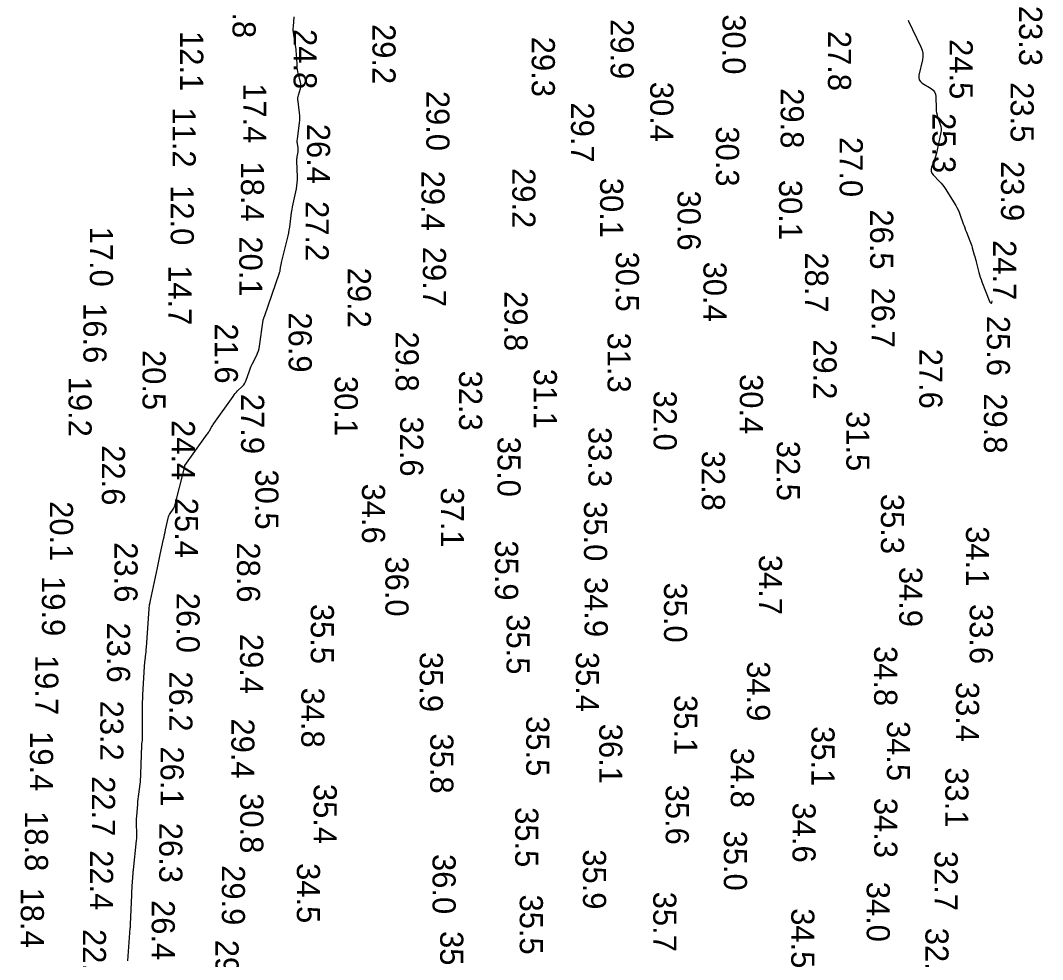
# Model space of a CAD drawing. Extents: x 1178573 to 1187098, y 693282 to 751751.
# Drawn here: x 1179064 to 1179617, y 708713 to 709221 of the extents above; entities that cross this region are included whole.
import ezdxf

# ---------------------------------------------------------------- set-up
doc = ezdxf.new("R2010")
doc.units = 0
doc.layers.add('V-HYDS-MAJR', color=7, linetype='Continuous')
doc.layers.add('V-HYDS-SOUN', color=7, linetype='Continuous')

msp = doc.modelspace()

# ---------------------------------------------------------------- linework, layer by layer
at = {"layer": 'V-HYDS-MAJR'}
for points in [[(1179122.48, 708712.53), (1179123.74, 708730.3), (1179123.75, 708730.48), (1179123.77, 708730.65), (1179123.78, 708730.83), (1179123.79, 708731), (1179123.83, 708731.7), (1179123.85, 708731.87), (1179123.86, 708732.05), (1179123.86, 708732.22), (1179123.87, 708732.4), (1179124.54, 708748.04), (1179124.59, 708749.27), (1179124.66, 708750.5), (1179124.73, 708751.73), (1179124.81, 708752.96), (1179125.28, 708760.05), (1179125.29, 708760.2), (1179125.3, 708760.34), (1179125.31, 708760.48), (1179125.33, 708760.62), (1179125.38, 708761.19), (1179125.4, 708761.34), (1179125.41, 708761.48), (1179125.43, 708761.62), (1179125.44, 708761.76), (1179127.13, 708777.71), (1179127.22, 708778.79), (1179127.28, 708779.86), (1179127.3, 708780.94), (1179127.28, 708782.02), (1179127.14, 708786.34), (1179127.12, 708787.42), (1179127.13, 708788.5), (1179127.17, 708789.58), (1179127.24, 708790.65), (1179127.75, 708797.37), (1179127.86, 708798.72), (1179128, 708800.06), (1179128.15, 708801.41), (1179128.32, 708802.75), (1179129.04, 708808.11), (1179129.21, 708809.46), (1179129.34, 708810.8), (1179129.43, 708812.15), (1179129.49, 708813.5), (1179129.99, 708829.25), (1179130.01, 708829.61), (1179130.03, 708829.98), (1179130.06, 708830.35), (1179130.1, 708830.72), (1179130.26, 708832.19), (1179130.3, 708832.56), (1179130.32, 708832.93), (1179130.34, 708833.29), (1179130.34, 708833.66), (1179130.26, 708850.45), (1179130.26, 708850.94), (1179130.27, 708851.44), (1179130.3, 708851.94), (1179130.33, 708852.43), (1179130.47, 708854.42), (1179130.5, 708854.91), (1179130.53, 708855.41), (1179130.56, 708855.91), (1179130.59, 708856.4), (1179131.41, 708871.76), (1179131.46, 708872.62), (1179131.53, 708873.47), (1179131.62, 708874.33), (1179131.72, 708875.19), (1179132.15, 708878.61), (1179132.25, 708879.46), (1179132.34, 708880.32), (1179132.41, 708881.17), (1179132.48, 708882.03), (1179133.88, 708902.93), (1179133.9, 708903.12), (1179133.91, 708903.3), (1179133.94, 708903.48), (1179133.96, 708903.67), (1179134.08, 708904.4), (1179134.11, 708904.58), (1179134.14, 708904.76), (1179134.17, 708904.94), (1179134.2, 708905.12), (1179134.46, 708906.44), (1179134.52, 708906.72), (1179134.57, 708906.99), (1179134.63, 708907.27), (1179134.69, 708907.55), (1179138.4, 708925.16), (1179138.79, 708926.97), (1179139.18, 708928.77), (1179139.57, 708930.58), (1179139.96, 708932.39), (1179141.77, 708940.68), (1179142.05, 708941.95), (1179142.32, 708943.23), (1179142.6, 708944.5), (1179142.87, 708945.77), (1179144.19, 708952.04), (1179144.36, 708952.71), (1179144.6, 708953.36), (1179144.9, 708953.97), (1179145.26, 708954.56), (1179146.85, 708956.87), (1179147.21, 708957.46), (1179147.53, 708958.07), (1179147.78, 708958.71), (1179147.98, 708959.38), (1179152.87, 708978.62), (1179152.91, 708978.79), (1179152.95, 708978.96), (1179152.99, 708979.13), (1179153.02, 708979.3), (1179153.2, 708980.28), (1179153.21, 708980.31), (1179153.21, 708980.34), (1179153.22, 708980.37), (1179153.22, 708980.4), (1179153.24, 708980.53), (1179153.25, 708980.56), (1179153.26, 708980.59), (1179153.27, 708980.62), (1179153.29, 708980.65), (1179165.32, 708997.48), (1179165.64, 708997.95), (1179165.96, 708998.43), (1179166.27, 708998.91), (1179166.56, 708999.4), (1179167.72, 709001.37), (1179168.02, 709001.86), (1179168.32, 709002.34), (1179168.64, 709002.82), (1179168.97, 709003.29), (1179179.35, 709017.98), (1179179.91, 709018.74), (1179180.51, 709019.48), (1179181.13, 709020.19), (1179181.78, 709020.88), (1179184.45, 709023.57), (1179185.07, 709024.27), (1179185.6, 709025.03), (1179186.04, 709025.84), (1179186.39, 709026.71), (1179187.94, 709031.26), (1179188.31, 709032.31), (1179188.73, 709033.34), (1179189.17, 709034.36), (1179189.65, 709035.37), (1179192.09, 709040.27), (1179192.61, 709041.43), (1179193.03, 709042.63), (1179193.36, 709043.85), (1179193.59, 709045.11), (1179195.6, 709059.25), (1179195.62, 709059.36), (1179195.64, 709059.47), (1179195.67, 709059.58), (1179195.7, 709059.69), (1179195.86, 709060.17), (1179195.89, 709060.26), (1179195.92, 709060.34), (1179195.95, 709060.42), (1179195.98, 709060.5), (1179196.13, 709060.83), (1179196.16, 709060.91), (1179196.2, 709060.99), (1179196.23, 709061.07), (1179196.26, 709061.16), (1179204.34, 709084.74), (1179204.38, 709084.87), (1179204.43, 709085.01), (1179204.47, 709085.14), (1179204.51, 709085.27), (1179204.69, 709085.79), (1179204.73, 709085.93), (1179204.76, 709086.06), (1179204.79, 709086.19), (1179204.82, 709086.33), (1179205.2, 709088.71), (1179205.27, 709089.15), (1179205.35, 709089.59), (1179205.45, 709090.03), (1179205.55, 709090.47), (1179209.03, 709104.9), (1179209.39, 709106.45), (1179209.7, 709108), (1179209.96, 709109.56), (1179210.18, 709111.14), (1179210.99, 709117.44), (1179211.21, 709119.01), (1179211.46, 709120.58), (1179211.75, 709122.14), (1179212.08, 709123.69), (1179213.54, 709130.28), (1179213.84, 709131.87), (1179214.03, 709133.46), (1179214.13, 709135.07), (1179214.13, 709136.68), (1179213.83, 709145.14), (1179213.83, 709145.77), (1179213.85, 709146.4), (1179213.92, 709147.02), (1179214.01, 709147.65), (1179214.47, 709150.26), (1179214.55, 709150.82), (1179214.57, 709151.39), (1179214.55, 709151.95), (1179214.49, 709152.52), (1179214.12, 709154.78), (1179214.05, 709155.34), (1179214.02, 709155.91), (1179214.03, 709156.48), (1179214.09, 709157.04), (1179215.24, 709166.01), (1179215.37, 709167.34), (1179215.41, 709168.66), (1179215.36, 709169.99), (1179215.23, 709171.32), (1179214.43, 709177.5), (1179214.36, 709178.39), (1179214.38, 709179.27), (1179214.5, 709180.15), (1179214.71, 709181.02), (1179215.75, 709184.47), (1179215.94, 709185.34), (1179216.02, 709186.21), (1179215.98, 709187.08), (1179215.81, 709187.95), (1179214.57, 709192.7), (1179214.33, 709193.75), (1179214.14, 709194.81), (1179214.01, 709195.88), (1179213.94, 709196.96), (1179213.76, 709201.28), (1179213.7, 709202.36), (1179213.61, 709203.43), (1179213.49, 709204.51), (1179213.34, 709205.58), (1179212.08, 709213.7), (1179211.94, 709214.8), (1179211.87, 709215.91), (1179211.87, 709217.01), (1179211.93, 709218.12), (1179212.4, 709223.4)], [(1179544.25, 709221.49), (1179544.5, 709220.9), (1179551.25, 709207.06), (1179551.92, 709205.35), (1179552.28, 709203.6), (1179552.33, 709201.82), (1179552.06, 709200), (1179550.16, 709191.74), (1179550.04, 709190.44), (1179550.29, 709189.3), (1179550.92, 709188.32), (1179551.94, 709187.5), (1179556.75, 709184.52), (1179557.81, 709183.7), (1179558.58, 709182.7), (1179559.06, 709181.54), (1179559.25, 709180.21), (1179559.46, 709173.53), (1179559.54, 709172.43), (1179559.69, 709171.35), (1179559.93, 709170.29), (1179560.24, 709169.24), (1179561.65, 709165.06), (1179561.94, 709164.02), (1179562.08, 709162.96), (1179562.08, 709161.89), (1179561.93, 709160.81), (1179560.09, 709151.42), (1179559.82, 709150.21), (1179559.51, 709149.01), (1179559.15, 709147.82), (1179558.73, 709146.65), (1179556.98, 709141.99), (1179556.7, 709140.86), (1179556.75, 709139.8), (1179557.13, 709138.81), (1179557.83, 709137.88), (1179561.28, 709134.3), (1179562.11, 709133.39), (1179562.9, 709132.43), (1179563.63, 709131.44), (1179564.31, 709130.41), (1179570.05, 709121.21), (1179570.71, 709120.08), (1179571.31, 709118.92), (1179571.84, 709117.72), (1179572.31, 709116.5), (1179574.14, 709111.3), (1179574.54, 709110.19), (1179574.95, 709109.08), (1179575.37, 709107.98), (1179575.8, 709106.88), (1179577.7, 709102.14), (1179578.05, 709101.22), (1179578.38, 709100.29), (1179578.69, 709099.35), (1179578.98, 709098.4), (1179580.08, 709094.61), (1179580.35, 709093.66), (1179580.61, 709092.7), (1179580.87, 709091.75), (1179581.11, 709090.79), (1179582.58, 709084.97), (1179582.92, 709083.68), (1179583.31, 709082.41), (1179583.74, 709081.16), (1179584.21, 709079.91), (1179588.56, 709068.94), (1179588.62, 709068.83), (1179588.69, 709068.74), (1179588.77, 709068.67), (1179588.88, 709068.61), (1179589.33, 709068.4), (1179589.43, 709068.37), (1179589.5, 709068.38), (1179589.55, 709068.44), (1179589.58, 709068.54), (1179589.7, 709069.61)]]:
    msp.add_lwpolyline(points, dxfattribs=at)

# ---------------------------------------------------------------- texts
at = {"layer": 'V-HYDS-SOUN'}
for s, p in [('18.8 ', (1179179.04, 709244.33)), ('23.3 ', (1179604.3, 709229.27)), ('29.9 ', (1179383.41, 709222.08)), ('30.0 ', (1179443.93, 709224.68)), ('12.1 ', (1179150.7, 709215.61)), ('24.8 ', (1179212.05, 709216.7)), ('29.2 ', (1179254.68, 709219.42)), ('27.8 ', (1179500.99, 709215.72)), ('29.3 ', (1179340.81, 709212.54)), ('24.5 ', (1179566.74, 709211.24)), ('17.4 ', (1179184.78, 709187.38)), ('30.4 ', (1179404.85, 709188.17)), ('23.5 ', (1179599.71, 709187.94)), ('29.0 ', (1179283.82, 709183.25)), ('29.8 ', (1179475.4, 709184.68)), ('29.7 ', (1179362.04, 709177)), ('11.2 ', (1179146.61, 709174.31)), ('25.3 ', (1179557.45, 709171.26)), ('26.4 ', (1179219.29, 709165.43)), ('30.3 ', (1179440.42, 709164.04)), ('27.0 ', (1179507.28, 709158.31)), ('18.4 ', (1179183.56, 709145.03)), ('23.9 ', (1179594.53, 709145.31)), ('29.4 ', (1179281.17, 709140.07)), ('29.2 ', (1179330.3, 709141.5)), ('12.0 ', (1179145.6, 709132.23)), ('30.1 ', (1179377.77, 709136.22)), ('30.1 ', (1179474.52, 709135.1)), ('30.6 ', (1179419.62, 709129.37)), ('27.2 ', (1179218.53, 709123.66)), ('26.5 ', (1179523.76, 709119.14)), ('17.0 ', (1179101.9, 709109.79)), ('20.1 ', (1179182.69, 709104.52)), ('29.7 ', (1179281.95, 709098.89)), ('24.7 ', (1179590.25, 709102.53)), ('30.5 ', (1179386.26, 709096.31)), ('28.7 ', (1179488.61, 709095.87)), ('14.7 ', (1179144.39, 709088.91)), ('29.2 ', (1179241.33, 709087.6)), ('30.4 ', (1179433.63, 709090.86)), ('26.7 ', (1179524.57, 709076.81)), ('29.8 ', (1179326.03, 709074.94)), ('16.6 ', (1179098.39, 709068.41)), ('26.9 ', (1179209.36, 709063.39)), ('25.6 ', (1179586.87, 709061.52)), ('21.6 ', (1179169.45, 709057.42)), ('29.8 ', (1179267.17, 709053.05)), ('31.3 ', (1179381.82, 709052.46)), ('29.2 ', (1179493.13, 709048.85)), ('27.6 ', (1179550.36, 709043.77)), ('20.5 ', (1179130.36, 709043.06)), ('31.1 ', (1179341.91, 709032.93)), ('19.2 ', (1179090.34, 709028.61)), ('30.1 ', (1179234.26, 709029)), ('32.3 ', (1179301.51, 709031.89)), ('30.4 ', (1179453.31, 709030.03)), ('32.0 ', (1179406.69, 709021.08)), ('27.9 ', (1179183.64, 709019.29)), ('29.8 ', (1179585.31, 709019.62)), ('31.5 ', (1179510.9, 709010.02)), ('24.4 ', (1179146.19, 709005.16)), ('32.6 ', (1179269.65, 709007.12)), ('33.3 ', (1179371.46, 709001.41)), ('35.0 ', (1179322.28, 708996.14)), ('32.5 ', (1179473.3, 708993.95)), ('22.6 ', (1179108.36, 708991.51)), ('32.8 ', (1179432.75, 708988.55)), ('30.5 ', (1179191.35, 708978.43)), ('34.6 ', (1179249.01, 708970.77)), ('37.1 ', (1179291.65, 708968.7)), ('20.1 ', (1179080.29, 708961.25)), ('25.4 ', (1179147.93, 708963.1)), ('35.0 ', (1179369.06, 708961.23)), ('35.3 ', (1179529.59, 708965.19)), ('34.1 ', (1179575.6, 708947.7)), ('23.6 ', (1179115.19, 708939.04)), ('28.6 ', (1179181.43, 708938.95)), ('35.9 ', (1179320.97, 708940.03)), ('36.0 ', (1179261.68, 708931.38)), ('34.7 ', (1179463.65, 708932.22)), ('34.9 ', (1179539.51, 708925.72)), ('19.9 ', (1179075.99, 708920.74)), ('34.9 ', (1179369.4, 708920.25)), ('35.0 ', (1179412.33, 708917.24)), ('26.0 ', (1179148.75, 708911.69)), ('35.5 ', (1179221.33, 708905.69)), ('33.6 ', (1179577.62, 708905.65)), ('35.5 ', (1179327.17, 708900.05)), ('23.6 ', (1179111.15, 708895.57)), ('29.4 ', (1179183.1, 708889.45)), ('34.8 ', (1179525.93, 708882.91)), ('19.7 ', (1179072.34, 708878.05)), ('35.9 ', (1179280.26, 708879.7)), ('35.4 ', (1179364.66, 708879.71)), ('34.9 ', (1179457.19, 708874.67)), ('26.2 ', (1179144.84, 708869.16)), ('33.4 ', (1179570.21, 708863.47)), ('34.8 ', (1179216.22, 708860.4)), ('35.1 ', (1179417.83, 708856.36)), ('23.2 ', (1179107.47, 708853.35)), ('35.5 ', (1179337.8, 708844.96)), ('29.4 ', (1179178.38, 708843.71)), ('36.1 ', (1179377.31, 708840.84)), ('35.1 ', (1179492.04, 708839.53)), ('34.5 ', (1179532.82, 708842.34)), ('19.4 ', (1179069.52, 708836.82)), ('35.8 ', (1179285.93, 708835.57)), ('26.1 ', (1179140.1, 708828.57)), ('34.8 ', (1179448.43, 708827.86)), ('33.1 ', (1179564.38, 708817.25)), ('22.7 ', (1179103.02, 708812.47)), ('35.4 ', (1179222.9, 708808.28)), ('35.6 ', (1179413.25, 708807.88)), ('30.8 ', (1179183.18, 708803.25)), ('34.3 ', (1179525.98, 708800.76)), ('35.5 ', (1179331.87, 708795.72)), ('34.6 ', (1179481.79, 708798.2)), ('18.8 ', (1179066.77, 708793.57)), ('26.3 ', (1179139.4, 708787.27)), ('35.0 ', (1179444.68, 708783.02)), ('22.4 ', (1179101.97, 708772.39)), ('35.9 ', (1179368.51, 708772.9)), ('36.0 ', (1179287.17, 708770.35)), ('32.7 ', (1179558.59, 708772.05)), ('29.9 ', (1179173.24, 708764.31)), ('34.5 ', (1179213.82, 708765.44)), ('18.4 ', (1179064.53, 708752.18)), ('34.0 ', (1179521.91, 708755.36)), ('26.4 ', (1179135.33, 708745.45)), ('35.5 ', (1179334.33, 708748.44)), ('35.7 ', (1179406.49, 708749.97)), ('34.5 ', (1179481.11, 708741.03)), ('22.0 ', (1179098.1, 708729.77)), ('35.6 ', (1179291.3, 708728.68)), ('32.8 ', (1179553.65, 708730.45)), ('29.6 ', (1179169.81, 708723.95))]:
    msp.add_text(s, height=12.5, rotation=270, dxfattribs=at).set_placement(p)

doc.saveas('drawing.dxf')
